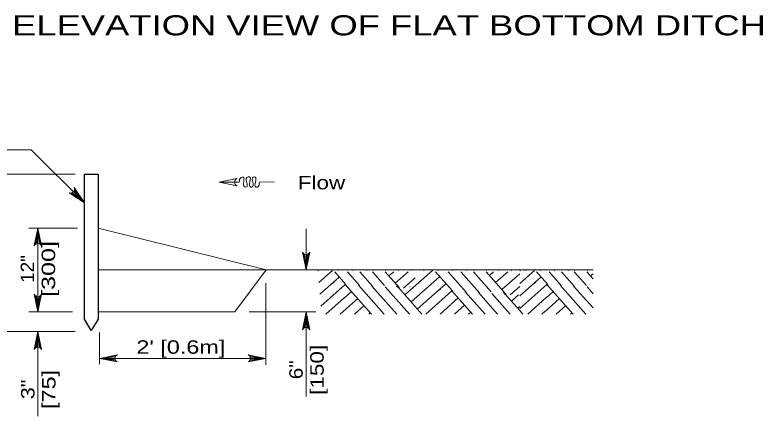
# Model space of a CAD drawing. Extents: x 1083.1 to 1117.1, y 672.5 to 716.5.
# Drawn here: x 1089.08 to 1097.99, y 705 to 709.78 of the extents above; entities that cross this region are included whole.
import ezdxf
from ezdxf.enums import TextEntityAlignment as Align

# ---------------------------------------------------------------- set-up
doc = ezdxf.new("R2010")
doc.units = 0
doc.header["$LTSCALE"] = 0.062
doc.layers.add('1', color=7, linetype='Continuous', lineweight=13)

msp = doc.modelspace()

# ---------------------------------------------------------------- linework, layer by layer
at = {"layer": '1'}
for p, q in [((1089.79942, 707.88417), (1087.16658, 707.88417)), ((1091.51342, 707.78775), (1091.75333, 707.78942)), ((1091.99317, 707.79108), (1092.17308, 707.79242)), ((1089.79125, 707.69858), (1089.90975, 707.54325)), ((1089.7495, 707.65975), (1089.90975, 707.54325)), ((1089.76358, 707.66342), (1089.90975, 707.54325)), ((1089.77825, 707.67333), (1089.90975, 707.54325)), ((1089.78292, 707.66875), (1089.90783, 707.54517)), ((1089.78642, 707.6845), (1089.90975, 707.54325)), ((1089.82492, 707.24317), (1089.24717, 707.24317)), ((1089.32742, 707.04967), (1089.3545, 707.24317)), ((1089.34083, 707.05617), (1089.3545, 707.24317)), ((1089.3545, 706.24317), (1089.3545, 707.24317)), ((1089.3545, 707.05817), (1089.3545, 707.24317)), ((1089.37192, 707.05475), (1089.3545, 707.24317)), ((1089.38442, 707.04733), (1089.3545, 707.24317)), ((1089.3545, 707.06475), (1089.3545, 707.2405)), ((1092.0715, 706.74317), (1090.0715, 707.24317)), ((1092.54867, 706.74317), (1092.54867, 707.23492)), ((1092.51875, 706.939), (1092.54867, 706.74317)), ((1092.53125, 706.93158), (1092.54867, 706.74317)), ((1092.57575, 706.93667), (1092.54867, 706.74317)), ((1092.56233, 706.93017), (1092.54867, 706.74317)), ((1092.54867, 706.92817), (1092.54867, 706.74317)), ((1092.54867, 706.92158), (1092.54867, 706.74583)), ((1092.0715, 706.74317), (1091.69992, 706.24317)), ((1092.0715, 706.74317), (1095.9665, 706.74317)), ((1092.69, 706.73458), (1092.69467, 706.73875)), ((1092.70117, 706.59417), (1092.86483, 706.73875)), ((1092.74508, 706.73883), (1092.74517, 706.73875)), ((1092.76175, 706.73875), (1092.76183, 706.73883)), ((1092.88967, 706.72208), (1093.02342, 706.57092)), ((1092.93192, 706.73875), (1092.93225, 706.73908)), ((1093.03975, 706.72225), (1093.18467, 706.55817)), ((1093.10158, 706.73875), (1093.10225, 706.73933)), ((1093.18975, 706.72233), (1093.34367, 706.54825)), ((1093.27158, 706.73875), (1093.2725, 706.7395)), ((1093.34025, 706.72242), (1093.48367, 706.56008)), ((1093.34517, 706.73967), (1093.34592, 706.73875)), ((1093.49033, 706.7225), (1093.66158, 706.52858)), ((1093.495, 706.73983), (1093.496, 706.73875)), ((1093.53508, 706.67167), (1093.5925, 706.7225)), ((1093.60958, 706.58742), (1093.76208, 706.72242)), ((1093.64517, 706.74), (1093.64633, 706.73875)), ((1093.72483, 706.44858), (1094.05283, 706.73875)), ((1093.79542, 706.74025), (1093.79675, 706.73875)), ((1093.94533, 706.74042), (1093.94683, 706.73875)), ((1093.95025, 706.73875), (1093.95217, 706.74042)), ((1094.09092, 706.72258), (1094.29383, 706.49325)), ((1094.11992, 706.73875), (1094.12208, 706.74067)), ((1094.24075, 706.72267), (1094.45592, 706.47942)), ((1094.29017, 706.73875), (1094.29258, 706.74092)), ((1094.391, 706.72275), (1094.61492, 706.46958)), ((1094.45983, 706.73875), (1094.4625, 706.74117)), ((1094.54158, 706.72275), (1094.754, 706.48233)), ((1094.54525, 706.74125), (1094.5475, 706.73875)), ((1094.69158, 706.72292), (1094.93283, 706.44992)), ((1094.69525, 706.74142), (1094.69767, 706.73875)), ((1094.73092, 706.67817), (1094.7815, 706.72292)), ((1094.80542, 706.59392), (1094.95133, 706.723)), ((1094.84517, 706.74167), (1094.84775, 706.73875)), ((1094.99558, 706.74183), (1094.99833, 706.73875)), ((1095.09175, 706.73433), (1095.09667, 706.73875)), ((1095.09175, 706.584), (1095.26692, 706.73875)), ((1095.14433, 706.74208), (1095.14725, 706.73875)), ((1095.16375, 706.73875), (1095.1675, 706.74208)), ((1095.29175, 706.72208), (1095.4255, 706.57092)), ((1095.334, 706.73875), (1095.338, 706.74233)), ((1095.44175, 706.72225), (1095.58675, 706.55817)), ((1095.50367, 706.73875), (1095.508, 706.74258)), ((1095.59183, 706.72233), (1095.74575, 706.54825)), ((1095.67358, 706.73875), (1095.67808, 706.74275)), ((1095.74233, 706.72242), (1095.88567, 706.56008)), ((1095.74433, 706.74283), (1095.748, 706.73875)), ((1095.89242, 706.7225), (1095.9665, 706.63858)), ((1095.89425, 706.74308), (1095.89808, 706.73875)), ((1092.71225, 706.454), (1092.93942, 706.65475)), ((1093.70992, 706.52558), (1093.84925, 706.64892)), ((1093.79933, 706.36433), (1094.13767, 706.66317)), ((1094.87992, 706.50975), (1095.09175, 706.69708)), ((1095.09175, 706.434), (1095.3415, 706.65475)), ((1095.93708, 706.67167), (1095.9665, 706.69767)), ((1092.07092, 706.58633), (1092.07092, 705.61333)), ((1092.72333, 706.31375), (1093.015, 706.57158)), ((1092.86283, 706.58092), (1092.88258, 706.59842)), ((1093.015, 706.57158), (1093.32742, 706.21858)), ((1093.17375, 706.56192), (1093.4775, 706.21858)), ((1093.33242, 706.55225), (1093.62783, 706.21858)), ((1093.49167, 706.5425), (1093.77825, 706.21858)), ((1093.62667, 706.55233), (1093.64292, 706.534)), ((1093.78575, 706.5425), (1093.78683, 706.54117)), ((1093.87383, 706.28017), (1094.21258, 706.57958)), ((1094.97925, 706.44708), (1095.09175, 706.5465)), ((1095.09175, 706.284), (1095.41708, 706.57158)), ((1095.26492, 706.58092), (1095.28458, 706.59842)), ((1095.41708, 706.57158), (1095.7295, 706.21858)), ((1095.57575, 706.56192), (1095.87958, 706.21858)), ((1095.7345, 706.55225), (1095.9665, 706.29017)), ((1095.89367, 706.5425), (1095.9665, 706.46017)), ((1093.00533, 706.41292), (1093.0895, 706.48742)), ((1093.65033, 706.53275), (1093.92833, 706.21858)), ((1093.97392, 706.21858), (1094.28542, 706.49392)), ((1094.13317, 706.50325), (1094.15192, 706.51983)), ((1094.28542, 706.49392), (1094.529, 706.21858)), ((1094.44408, 706.48425), (1094.67917, 706.21858)), ((1094.60283, 706.4745), (1094.82925, 706.21858)), ((1094.762, 706.46475), (1094.97983, 706.21858)), ((1094.89792, 706.47367), (1094.91325, 706.45625)), ((1094.92075, 706.45508), (1095.09175, 706.26175)), ((1095.057, 706.46375), (1095.05725, 706.4635)), ((1095.40742, 706.41292), (1095.49158, 706.48742)), ((1089.32458, 706.439), (1089.3545, 706.24317)), ((1089.33708, 706.43158), (1089.3545, 706.24317)), ((1089.38158, 706.43667), (1089.3545, 706.24317)), ((1089.36817, 706.43017), (1089.3545, 706.24317)), ((1089.3545, 706.42817), (1089.3545, 706.24317)), ((1089.3545, 706.42158), (1089.3545, 706.24583)), ((1092.78542, 706.21858), (1093.00192, 706.41008)), ((1092.99558, 706.254), (1093.16425, 706.40317)), ((1094.27567, 706.33525), (1094.35992, 706.40975)), ((1094.99525, 706.37083), (1095.07942, 706.44533)), ((1095.18742, 706.21858), (1095.40392, 706.41008)), ((1095.39767, 706.254), (1095.56633, 706.40317)), ((1093.12525, 706.21858), (1093.23875, 706.319)), ((1094.14358, 706.21858), (1094.27225, 706.33242)), ((1094.31383, 706.21858), (1094.43467, 706.3255)), ((1095.06975, 706.28667), (1095.09175, 706.30608)), ((1095.52733, 706.21858), (1095.64083, 706.319)), ((1089.76717, 706.24317), (1089.24717, 706.24317)), ((1090.0715, 706.24317), (1091.69992, 706.24317)), ((1091.87183, 706.24317), (1092.66492, 706.24317)), ((1092.52158, 706.04967), (1092.54867, 706.24317)), ((1092.535, 706.05617), (1092.54867, 706.24317)), ((1092.54867, 705.23583), (1092.54867, 706.24317)), ((1092.54867, 706.05817), (1092.54867, 706.24317)), ((1092.56608, 706.05475), (1092.54867, 706.24317)), ((1092.57858, 706.04733), (1092.54867, 706.24317)), ((1092.54867, 706.06475), (1092.54867, 706.2405)), ((1092.95558, 706.21858), (1092.99217, 706.25092)), ((1093.295, 706.21858), (1093.31325, 706.23483)), ((1094.4835, 706.21858), (1094.50917, 706.24133)), ((1095.09175, 706.26042), (1095.12875, 706.21858)), ((1095.35767, 706.21858), (1095.39425, 706.25092)), ((1095.69708, 706.21858), (1095.71533, 706.23483)), ((1089.79942, 706.00833), (1087.16658, 706.00833)), ((1089.32742, 705.81675), (1089.3545, 706.01025)), ((1089.34083, 705.82325), (1089.3545, 706.01025)), ((1089.3545, 705.00292), (1089.3545, 706.01025)), ((1089.3545, 705.82525), (1089.3545, 706.01025)), ((1089.37192, 705.82183), (1089.3545, 706.01025)), ((1089.38442, 705.81442), (1089.3545, 706.01025)), ((1089.3545, 705.83183), (1089.3545, 706.00758)), ((1090.08767, 705.99642), (1090.08767, 705.621)), ((1090.2835, 705.71983), (1090.08767, 705.68992)), ((1090.27608, 705.70733), (1090.08767, 705.68992)), ((1092.07092, 705.68992), (1090.08767, 705.68992)), ((1090.27267, 705.68992), (1090.08767, 705.68992)), ((1090.27467, 705.67625), (1090.08767, 705.68992)), ((1090.28117, 705.66283), (1090.08767, 705.68992)), ((1090.26608, 705.68992), (1090.09033, 705.68992)), ((1091.87508, 705.66), (1092.07092, 705.68992)), ((1091.87742, 705.717), (1092.07092, 705.68992)), ((1091.8825, 705.6725), (1092.07092, 705.68992)), ((1091.88392, 705.70358), (1092.07092, 705.68992)), ((1091.88592, 705.68992), (1092.07092, 705.68992)), ((1091.8925, 705.68992), (1092.06825, 705.68992))]:
    msp.add_line(p, q, dxfattribs=at)
for points in [[(1089.90975, 707.54325), (1089.27583, 708.17617), (1088.893, 708.17617)], [(1091.72558, 707.74683), (1091.51342, 707.78775), (1091.725, 707.83158), (1091.725, 707.83142)], [(1089.72775, 707.66317), (1089.90975, 707.54325), (1089.78783, 707.724)], [(1089.39725, 707.02942), (1089.3545, 707.24317), (1089.31175, 707.02942)], [(1092.50592, 706.95692), (1092.54867, 706.74317), (1092.59142, 706.95692)], [(1089.31175, 706.45692), (1089.3545, 706.24317), (1089.39725, 706.45692)], [(1092.59142, 706.02942), (1092.54867, 706.24317), (1092.50592, 706.02942)], [(1089.39725, 705.7965), (1089.3545, 706.01025), (1089.31175, 705.7965)], [(1090.30142, 705.73267), (1090.08767, 705.68992), (1090.30142, 705.64717)], [(1091.85717, 705.64717), (1092.07092, 705.68992), (1091.85717, 705.73267)]]:
    msp.add_lwpolyline(points, dxfattribs=at)
at = {"layer": '1', "lineweight": 25}
msp.add_lwpolyline([(1089.90975, 707.88417), (1090.0715, 707.88417), (1090.0715, 706.15575), (1089.99058, 706.02367), (1089.90975, 706.15575)], close=True, dxfattribs=at)
at = {"layer": '1'}
for points in [[(1090.0715, 707.24317), (1090.0715, 706.74317), (1092.0715, 706.74317)], [(1090.0715, 706.74317), (1090.0715, 706.24317), (1091.69992, 706.24317), (1092.0715, 706.74317)]]:
    msp.add_lwpolyline(points, close=True, dxfattribs=at)
for centre, radius, start, end in [((1091.74258, 707.78922), 0.04573, 112.49372, 248.31985), ((1089.74557, 707.70576), 0.04613, 247.39167, 23.21779), ((1089.35445, 707.01216), 0.04613, 22.08605, 157.91218), ((1092.54871, 706.97417), 0.04613, 202.08605, 337.91218), ((1089.35455, 706.47417), 0.04613, 202.08605, 337.91218), ((1092.54862, 706.01216), 0.04613, 22.08605, 157.91218), ((1089.35445, 705.77924), 0.04613, 22.08605, 157.91218), ((1090.31867, 705.68987), 0.04613, 112.08605, 247.91218), ((1091.83991, 705.68996), 0.04613, 292.08605, 67.91218)]:
    msp.add_arc(centre, radius, start, end, dxfattribs=at)
msp.add_spline([(1091.75333, 707.78942), (1091.77342, 707.84425), (1091.7985, 707.84775), (1091.81433, 707.73492), (1091.83742, 707.7325), (1091.84342, 707.84542), (1091.87533, 707.85375), (1091.88642, 707.73142), (1091.90667, 707.73225), (1091.9175, 707.84933), (1091.9405, 707.85008), (1091.94883, 707.7305), (1091.96908, 707.73142), (1091.99317, 707.79108)], degree=3, dxfattribs=at)

# ---------------------------------------------------------------- texts
at = {"layer": '1', "width": 1.35}
msp.add_text('ELEVATION VIEW OF FLAT BOTTOM DITCH', height=0.24, dxfattribs=at).set_placement((1089.0465, 709.53792))
at = {"layer": '1'}
for s, width, p in [('Flow', 1.25, (1092.7315, 707.704)), ("2' [0.6m]", 1.3, (1091.05662, 705.74517))]:
    msp.add_text(s, height=0.16, dxfattribs=dict(at, width=width)).set_placement(p, align=Align.CENTER)
for s, width, p in [('[300]', 1.4, (1089.55942, 706.755)), ('12"', 1.05, (1089.30942, 706.755)), ('[150]', 1.25, (1092.75808, 705.5535)), ('6"', 1.15, (1092.50808, 705.55354)), ('[75]', 1.3, (1089.56392, 705.32054)), ('3"', 1.2, (1089.31392, 705.32058))]:
    msp.add_text(s, height=0.16, rotation=90, dxfattribs=dict(at, width=width)).set_placement(p, align=Align.CENTER)

doc.saveas('drawing.dxf')
